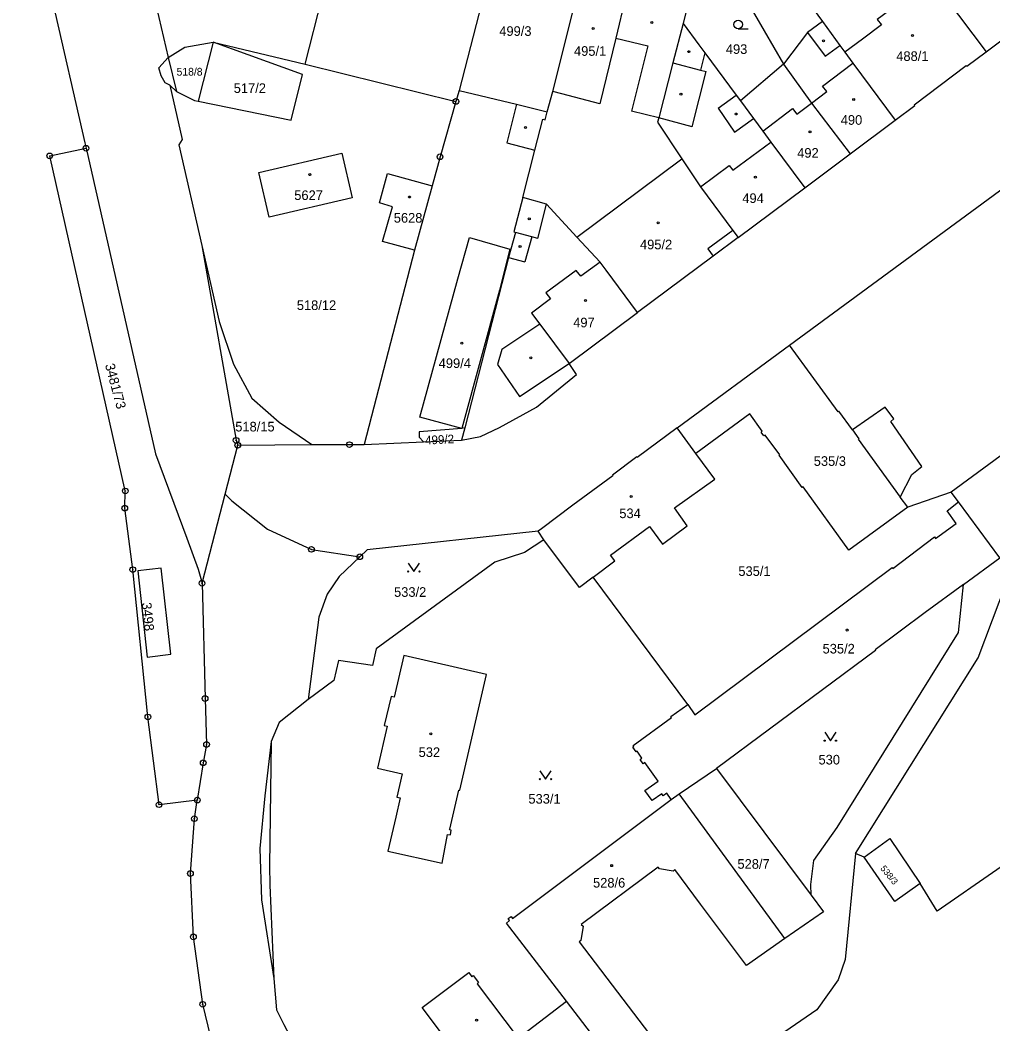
# Model space of a CAD drawing. Extents: x -733394 to -722299, y -1082822 to -1075049.
# Drawn here: x -728736.2 to -728564.5, y -1079876.8 to -1079699.5 of the extents above; entities that cross this region are included whole.
import ezdxf

# ---------------------------------------------------------------- set-up
doc = ezdxf.new("R2010")
doc.units = 0
for name, color, linetype in [('Hranice parcel', 7, 'Continuous'), ('Parcelní čísla', 7, 'Continuous'), ('Vnitřní kresba', 7, 'Continuous'), ('Značky bodu BP', 7, 'Continuous'), ('Značky budov', 7, 'Continuous'), ('Značky kultur', 7, 'Continuous')]:
    doc.layers.add(name, color=color, linetype=linetype)

msp = doc.modelspace()

# ---------------------------------------------------------------- linework, layer by layer
at = {"layer": 'Hranice parcel'}
for p, q in [((-728600.37, -1079756.93), (-728481.03, -1079668.98)), ((-728685.9, -1079707.28), (-728676.7, -1079670.77)), ((-728615.13, -1079683.71), (-728601.43, -1079707.28)), ((-728600.39, -1079691.8), (-728594.58, -1079699.77)), ((-728565.68, -1079705.08), (-728549.64, -1079693.06)), ((-728712.73, -1079694.7), (-728710.07, -1079706.09)), ((-728574.05, -1079693.93), (-728565.68, -1079705.08)), ((-728618.23, -1079696.26), (-728619.19, -1079700.08)), ((-728702.17, -1079703.39), (-728704.81, -1079713.82)), ((-728702.17, -1079703.39), (-728685.9, -1079707.28)), ((-728710.07, -1079706.09), (-728708.63, -1079712.09)), ((-728685.9, -1079707.28), (-728659.29, -1079713.87)), ((-728601.43, -1079707.28), (-728609.07, -1079713.76)), ((-728589.67, -1079723.1), (-728581.71, -1079717.14)), ((-728597.69, -1079729.14), (-728589.67, -1079723.1)), ((-728637.95, -1079737.82), (-728619.38, -1079724.02)), ((-728663.46, -1079728.74), (-728666.6, -1079740.15)), ((-728609.45, -1079737.9), (-728597.69, -1079729.14)), ((-728666.6, -1079740.15), (-728675.49, -1079774.47)), ((-728620.2, -1079771.52), (-728600.37, -1079756.93)), ((-728657.74, -1079771.52), (-728658.3, -1079773.67)), ((-728616.93, -1079776.02), (-728620.2, -1079771.52)), ((-728700.04, -1079783.2), (-728697.81, -1079774.58)), ((-728697.81, -1079774.58), (-728684.74, -1079774.48)), ((-728675.49, -1079774.47), (-728665.01, -1079773.97)), ((-728665.01, -1079773.97), (-728658.3, -1079773.67)), ((-728704.12, -1079798.96), (-728700.04, -1079783.2)), ((-728571.82, -1079782.9), (-728579.52, -1079785.52)), ((-728570.57, -1079784.59), (-728571.82, -1079782.9)), ((-728563.27, -1079794.45), (-728570.57, -1079784.59)), ((-728643.75, -1079791.27), (-728644.78, -1079789.76)), ((-728569.69, -1079799.17), (-728563.27, -1079794.45)), ((-728618.36, -1079820.39), (-728635.06, -1079797.91)), ((-728619.87, -1079836.15), (-728613.3, -1079831.66)), ((-728613.3, -1079831.66), (-728596.59, -1079854.04)), ((-728621.29, -1079837.13), (-728619.87, -1079836.15)), ((-728601.22, -1079861.71), (-728619.87, -1079836.15)), ((-728587.19, -1079847.34), (-728588.73, -1079846.69)), ((-728648.31, -1079879.32), (-728639.77, -1079872.79))]:
    msp.add_line(p, q, dxfattribs=at)
for points in [[(-728736.24, -1079671.17), (-728724.82, -1079721.18), (-728724.6, -1079722.13)], [(-728647.5, -1079730.8), (-728645.37, -1079722.49), (-728643.96, -1079716.99), (-728643.51, -1079717.1), (-728643.19, -1079715.67), (-728642.19, -1079712.1), (-728638.7, -1079698.26), (-728637.07, -1079691.73), (-728636.65, -1079691.83)], [(-728574.62, -1079693.18), (-728581.09, -1079698.03), (-728581.81, -1079697.07), (-728584.9, -1079699.36), (-728584.17, -1079700.33), (-728587.53, -1079702.85), (-728590.64, -1079705.18)], [(-728654.26, -1079694.49), (-728658.73, -1079711.9), (-728659.29, -1079713.87)], [(-728619.19, -1079700.08), (-728620.96, -1079707.02), (-728623.45, -1079716.76), (-728623.71, -1079717.51), (-728619.38, -1079724.02)], [(-728619.19, -1079700.08), (-728616.37, -1079703.87), (-728615.34, -1079705.27), (-728609.8, -1079712.78), (-728609.07, -1079713.76)], [(-728594.58, -1079699.77), (-728597.21, -1079701.68), (-728601.43, -1079707.28)], [(-728594.58, -1079699.77), (-728591.52, -1079703.97), (-728590.64, -1079705.18)], [(-728461.74, -1079701.6), (-728474.16, -1079710.73), (-728473.29, -1079711.95), (-728473.96, -1079712.56), (-728473.83, -1079712.73), (-728488.37, -1079723.47), (-728489.45, -1079722.05), (-728493.6, -1079725.15), (-728492.57, -1079726.56), (-728507.86, -1079737.87), (-728508.12, -1079737.52), (-728514.31, -1079742.12), (-728515.03, -1079741.15), (-728518.25, -1079743.53), (-728517.53, -1079744.5), (-728523.81, -1079749.15), (-728523.56, -1079749.48), (-728558.3, -1079775.23), (-728559.4, -1079773.75), (-728571.82, -1079782.9)], [(-728710.07, -1079706.09), (-728707.17, -1079704.26), (-728702.17, -1079703.39)], [(-728704.81, -1079713.82), (-728688.39, -1079717.19), (-728686.35, -1079709.09), (-728702.17, -1079703.39)], [(-728590.64, -1079705.18), (-728589.19, -1079707.1), (-728581.71, -1079717.14)], [(-728581.71, -1079717.14), (-728578.28, -1079714.56), (-728578.36, -1079714.44), (-728569.18, -1079707.53), (-728569.09, -1079707.65), (-728565.68, -1079705.08)], [(-728601.43, -1079707.28), (-728596.5, -1079714.16), (-728589.67, -1079723.1)], [(-728708.63, -1079712.09), (-728709.79, -1079711.01), (-728707.61, -1079720.57), (-728708.21, -1079721.53), (-728704.16, -1079739.32)], [(-728708.63, -1079712.09), (-728705.47, -1079713.67), (-728704.81, -1079713.82)], [(-728659.29, -1079713.87), (-728662.09, -1079723.64), (-728663.46, -1079728.74)], [(-728609.07, -1079713.76), (-728606.77, -1079716.88), (-728605.12, -1079719.11), (-728603.68, -1079721.05), (-728597.69, -1079729.14)], [(-728704.95, -1079837.26), (-728711.71, -1079838.07), (-728713.67, -1079822.58), (-728716.34, -1079796.56), (-728717.75, -1079785.69), (-728717.66, -1079782.66), (-728731.01, -1079723.47), (-728724.6, -1079722.13)], [(-728724.6, -1079722.13), (-728712.34, -1079776.13), (-728706.81, -1079790.97), (-728704.81, -1079796.45), (-728704.12, -1079798.96)], [(-728692.28, -1079734.29), (-728694.09, -1079726.39), (-728679.41, -1079723.02), (-728677.59, -1079730.91), (-728692.28, -1079734.29)], [(-728619.38, -1079724.02), (-728616.09, -1079728.97), (-728614.93, -1079730.55), (-728610.39, -1079736.64), (-728609.45, -1079737.9)], [(-728666.6, -1079740.15), (-728672.24, -1079738.61), (-728670.5, -1079732.46), (-728672.81, -1079731.78), (-728671.39, -1079726.56), (-728663.46, -1079728.74)], [(-728647.5, -1079730.8), (-728649.07, -1079736.92), (-728648.79, -1079736.99), (-728649.98, -1079741.42), (-728657.74, -1079771.52)], [(-728637.95, -1079737.82), (-728643.28, -1079732.02), (-728647.5, -1079730.8)], [(-728651.59, -1079747.22), (-728658.27, -1079771.62), (-728665.65, -1079769.6), (-728658.97, -1079745.2), (-728656.9, -1079737.89), (-728649.76, -1079739.93), (-728651.59, -1079747.22)], [(-728627.22, -1079751.12), (-728632.77, -1079743.66), (-728633.8, -1079742.27), (-728637.95, -1079737.82)], [(-728609.45, -1079737.9), (-728613.85, -1079741.18), (-728627.22, -1079751.12)], [(-728704.16, -1079739.32), (-728701.09, -1079752.75), (-728698.56, -1079760.27), (-728695.31, -1079766.27), (-728690.52, -1079770.5), (-728684.74, -1079774.48)], [(-728704.16, -1079739.32), (-728698.1, -1079773.71), (-728697.81, -1079774.58)], [(-728658.3, -1079773.67), (-728654.94, -1079773.04), (-728651.58, -1079771.48), (-728645.08, -1079767.85), (-728637.99, -1079762.09), (-728639.3, -1079760.14), (-728627.22, -1079751.12)], [(-728579.52, -1079785.52), (-728580.83, -1079783.73), (-728578.78, -1079779.77), (-728577.02, -1079778.36), (-728582.48, -1079770.38), (-728581.95, -1079769.92), (-728583.49, -1079767.87), (-728589.28, -1079771.89), (-728591.7, -1079768.57), (-728591.82, -1079768.66), (-728600.37, -1079756.93)], [(-728579.52, -1079785.52), (-728589.92, -1079793.09), (-728597.99, -1079781.94), (-728598.13, -1079782.04), (-728602.24, -1079776.36), (-728602.1, -1079776.27), (-728604.69, -1079772.8), (-728604.91, -1079772.95), (-728605.41, -1079772.26), (-728605.2, -1079772.1), (-728607.42, -1079769.04), (-728616.93, -1079776.02)], [(-728657.74, -1079771.52), (-728658.27, -1079771.62), (-728665.8, -1079772.22), (-728665.75, -1079773.15), (-728665.01, -1079773.97)], [(-728620.2, -1079771.52), (-728627.31, -1079776.75), (-728627.36, -1079776.66), (-728631.66, -1079779.89), (-728631.6, -1079779.98), (-728638.64, -1079785.16), (-728644.18, -1079789.32), (-728644.78, -1079789.76)], [(-728684.74, -1079774.48), (-728678.09, -1079774.48), (-728675.49, -1079774.47)], [(-728635.06, -1079797.91), (-728631.22, -1079794.99), (-728631.98, -1079794.01), (-728625.09, -1079788.96), (-728622.82, -1079792.05), (-728618.44, -1079788.84), (-728620.71, -1079785.65), (-728613.58, -1079780.58), (-728616.93, -1079776.02)], [(-728700.04, -1079783.2), (-728698.86, -1079784.41), (-728692.53, -1079789.41), (-728684.8, -1079792.98), (-728676.26, -1079794.29)], [(-728618.36, -1079820.39), (-728617.08, -1079822.2), (-728582.27, -1079796.16), (-728582.12, -1079796.36), (-728574.81, -1079790.77), (-728574.6, -1079791.05), (-728570.98, -1079788.4), (-728572.57, -1079786.16), (-728570.57, -1079784.59)], [(-728644.78, -1079789.76), (-728674.95, -1079793.03), (-728676.26, -1079794.29)], [(-728643.75, -1079791.27), (-728647.19, -1079793.53), (-728652.44, -1079795.23), (-728673.39, -1079810.55), (-728674.01, -1079813.51), (-728680, -1079812.61), (-728680.83, -1079816.15), (-728685.38, -1079819.49)], [(-728635.06, -1079797.91), (-728637.47, -1079799.74), (-728643.75, -1079791.27)], [(-728676.26, -1079794.29), (-728679.91, -1079797.78), (-728682.01, -1079800.9), (-728683.5, -1079804.93), (-728685.38, -1079819.49)], [(-728711.35, -1079796.28), (-728715.46, -1079796.75), (-728713.82, -1079812.01), (-728709.6, -1079811.46), (-728711.35, -1079796.28)], [(-728704.12, -1079798.96), (-728703.58, -1079819.32), (-728703.32, -1079827.43), (-728703.91, -1079830.67), (-728704.95, -1079837.26)], [(-728569.69, -1079799.17), (-728576.43, -1079804.11), (-728585.24, -1079810.75), (-728585.18, -1079810.83), (-728613.3, -1079831.66)], [(-728596.59, -1079854.04), (-728596.65, -1079852.18), (-728596.07, -1079847.92), (-728591.97, -1079842.08), (-728570.58, -1079807.66), (-728569.69, -1079799.17)], [(-728588.73, -1079846.69), (-728567.06, -1079812.14), (-728562.01, -1079798.71)], [(-728661.74, -1079848.42), (-728660.75, -1079843.31), (-728660.27, -1079843.41), (-728660.11, -1079842.58), (-728660.4, -1079842.52), (-728660.38, -1079842.42), (-728658.76, -1079835.48), (-728658.62, -1079835.52), (-728653.86, -1079815.1), (-728668.48, -1079811.7), (-728670.19, -1079819.07), (-728670.73, -1079818.95), (-728671.93, -1079824.1), (-728671.41, -1079824.23), (-728673.12, -1079831.61), (-728668.78, -1079832.62), (-728669.73, -1079836.74), (-728669.12, -1079836.88), (-728669.92, -1079840.3), (-728671.3, -1079846.27), (-728661.74, -1079848.42)], [(-728685.38, -1079819.49), (-728690.49, -1079823.57), (-728691.93, -1079826.93), (-728692.21, -1079848.9), (-728692.12, -1079852.26), (-728691.43, -1079868.79), (-728690.98, -1079874.32), (-728689.69, -1079876.88), (-728686.54, -1079882.81), (-728681.95, -1079889.46), (-728677.3, -1079895.69), (-728672.31, -1079904.55), (-728667.7, -1079914.61), (-728664.97, -1079923.35), (-728665.49, -1079935.45), (-728666.25, -1079938.93), (-728675.19, -1079953.37), (-728681.79, -1079965.59), (-728682.06, -1079967.06)], [(-728621.29, -1079837.13), (-728622.07, -1079836.02), (-728622.71, -1079836.48), (-728622.94, -1079836.16), (-728624.66, -1079837.36), (-728625.92, -1079835.56), (-728623.6, -1079833.94), (-728625.92, -1079830.61), (-728626.24, -1079830.84), (-728626.78, -1079830.08), (-728626.45, -1079829.85), (-728627.29, -1079828.64), (-728627.46, -1079828.76), (-728628.06, -1079827.91), (-728627.9, -1079827.79), (-728628.01, -1079827.63), (-728621.21, -1079822.7), (-728621.36, -1079822.5), (-728618.36, -1079820.39)], [(-728542.72, -1079834.95), (-728574.3, -1079856.88), (-728577.3, -1079851.98)], [(-728692.61, -1079900.87), (-728697.81, -1079892.26), (-728701.6, -1079883.03), (-728704, -1079873.33), (-728705.64, -1079861.43), (-728706.17, -1079850.23), (-728705.47, -1079840.55), (-728704.95, -1079837.26)], [(-728639.77, -1079872.79), (-728650.37, -1079858.97), (-728649.8, -1079858.54), (-728650.06, -1079858.2), (-728649.54, -1079857.81), (-728649.27, -1079858.16), (-728621.29, -1079837.13)], [(-728587.19, -1079847.34), (-728582.69, -1079844.05), (-728577.3, -1079851.98)], [(-728588.73, -1079846.69), (-728590.57, -1079865.42), (-728591.78, -1079868.98), (-728595.58, -1079874.31), (-728604.06, -1079880.15), (-728602.36, -1079880.57), (-728608.62, -1079902.34), (-728611.09, -1079901.64)], [(-728577.3, -1079851.98), (-728581.81, -1079855.16), (-728587.19, -1079847.34)], [(-728601.22, -1079861.71), (-728607.99, -1079866.45), (-728616.08, -1079855.63), (-728620.63, -1079849.54), (-728620.94, -1079849.84), (-728623.34, -1079849.43), (-728623.55, -1079849.1), (-728637.15, -1079859.21), (-728636.84, -1079859.55), (-728637.25, -1079862.05), (-728637.54, -1079862.27), (-728620.25, -1079885.03), (-728622.03, -1079886.35), (-728621.8, -1079886.66), (-728622.34, -1079887.06), (-728622.57, -1079886.76), (-728626.69, -1079889.83), (-728639.77, -1079872.79)], [(-728596.59, -1079854.04), (-728594.37, -1079857.01), (-728601.22, -1079861.71)], [(-728656.47, -1079885.56), (-728665.24, -1079873.88), (-728657.03, -1079867.74), (-728656.49, -1079868.45), (-728656.22, -1079868.25), (-728655.28, -1079869.5), (-728655.55, -1079869.7), (-728648.31, -1079879.32)]]:
    msp.add_lwpolyline(points, dxfattribs=at)
at = {"layer": 'Vnitřní kresba'}
for p, q in [((-728628.91, -1079693.69), (-728631.07, -1079702.68)), ((-728597.21, -1079701.68), (-728594.11, -1079705.86)), ((-728631.07, -1079702.68), (-728633.85, -1079714.28)), ((-728631.07, -1079702.68), (-728625.43, -1079704.03)), ((-728625.43, -1079704.03), (-728628.31, -1079715.6)), ((-728594.11, -1079705.86), (-728591.52, -1079703.97)), ((-728615.34, -1079705.27), (-728616.1, -1079708.32)), ((-728620.96, -1079707.02), (-728616.1, -1079708.32)), ((-728594.55, -1079711.14), (-728589.19, -1079707.1)), ((-728617.56, -1079718.33), (-728615.11, -1079708.57)), ((-728616.1, -1079708.32), (-728615.11, -1079708.57)), ((-728593.82, -1079712.09), (-728594.55, -1079711.14)), ((-728658.73, -1079711.9), (-728648.62, -1079714.35)), ((-728640.56, -1079712.53), (-728642.19, -1079712.1)), ((-728633.85, -1079714.28), (-728640.56, -1079712.53)), ((-728613, -1079715.05), (-728609.8, -1079712.78)), ((-728596.5, -1079714.16), (-728593.82, -1079712.09)), ((-728648.62, -1079714.35), (-728650.32, -1079721.16)), ((-728648.62, -1079714.35), (-728643.19, -1079715.67)), ((-728599.08, -1079716.11), (-728596.5, -1079714.16)), ((-728623.45, -1079716.76), (-728628.31, -1079715.6)), ((-728613, -1079715.05), (-728610.09, -1079719.27)), ((-728605.12, -1079719.11), (-728599.84, -1079715.13)), ((-728599.84, -1079715.13), (-728599.08, -1079716.11)), ((-728617.56, -1079718.33), (-728623.45, -1079716.76)), ((-728610.09, -1079719.27), (-728606.77, -1079716.88)), ((-728650.32, -1079721.16), (-728645.37, -1079722.49)), ((-728610.37, -1079725.98), (-728603.68, -1079721.05)), ((-728616.09, -1079728.97), (-728611.05, -1079725.17)), ((-728611.05, -1079725.17), (-728610.37, -1079725.98)), ((-728644.85, -1079738.06), (-728643.28, -1079732.02)), ((-728645.89, -1079737.78), (-728648.79, -1079736.99)), ((-728645.89, -1079737.78), (-728647.1, -1079742.2)), ((-728644.85, -1079738.06), (-728645.89, -1079737.78)), ((-728610.39, -1079736.64), (-728614.79, -1079739.92)), ((-728649.98, -1079741.42), (-728647.1, -1079742.2)), ((-728614.79, -1079739.92), (-728613.85, -1079741.18)), ((-728633.8, -1079742.27), (-728637.21, -1079744.75)), ((-728638.05, -1079743.73), (-728643.4, -1079747.67)), ((-728637.21, -1079744.75), (-728638.05, -1079743.73)), ((-728643.4, -1079747.67), (-728642.61, -1079748.73)), ((-728642.61, -1079748.73), (-728645.96, -1079751.23)), ((-728645.96, -1079751.23), (-728644.45, -1079753.18)), ((-728644.45, -1079753.18), (-728651.2, -1079757.68)), ((-728644.45, -1079753.18), (-728639.3, -1079760.14)), ((-728651.2, -1079757.68), (-728651.94, -1079760.33)), ((-728651.94, -1079760.33), (-728648.09, -1079765.97)), ((-728648.09, -1079765.97), (-728639.3, -1079760.14)), ((-728589.28, -1079771.89), (-728588.14, -1079773.44)), ((-728588.14, -1079773.44), (-728588.27, -1079773.52)), ((-728588.27, -1079773.52), (-728580.83, -1079783.73)), ((-728691.93, -1079826.93), (-728693.02, -1079836.53)), ((-728693.02, -1079836.53), (-728693.91, -1079845.81)), ((-728693.91, -1079845.81), (-728693.59, -1079854.89)), ((-728693.59, -1079854.89), (-728691.43, -1079868.79))]:
    msp.add_line(p, q, dxfattribs=at)
msp.add_lwpolyline([(-728709.79, -1079711.01), (-728710.63, -1079710.58), (-728711.33, -1079709.36), (-728711.74, -1079707.91), (-728710.07, -1079706.09)], dxfattribs=at)
at = {"layer": 'Značky bodu BP'}
for centre, radius in [((-728659.29, -1079713.87), 0.5), ((-728659.29, -1079713.87), 0.0303), ((-728724.6, -1079722.13), 0.5), ((-728731.01, -1079723.47), 0.5), ((-728731.01, -1079723.47), 0.0303), ((-728724.6, -1079722.13), 0.0303), ((-728662.09, -1079723.64), 0.5), ((-728662.09, -1079723.64), 0.0303), ((-728698.1, -1079773.71), 0.5), ((-728697.81, -1079774.58), 0.5), ((-728698.1, -1079773.71), 0.0303), ((-728697.81, -1079774.58), 0.0303), ((-728678.09, -1079774.48), 0.5), ((-728678.09, -1079774.48), 0.0303), ((-728717.66, -1079782.66), 0.5), ((-728717.66, -1079782.66), 0.0303), ((-728717.75, -1079785.69), 0.5), ((-728717.75, -1079785.69), 0.0303), ((-728684.8, -1079792.98), 0.5), ((-728684.8, -1079792.98), 0.0303), ((-728676.26, -1079794.29), 0.5), ((-728676.26, -1079794.29), 0.0303), ((-728716.34, -1079796.56), 0.5), ((-728716.34, -1079796.56), 0.0303), ((-728704.12, -1079798.96), 0.5), ((-728704.12, -1079798.96), 0.0303), ((-728703.58, -1079819.32), 0.5), ((-728703.58, -1079819.32), 0.0303), ((-728713.67, -1079822.58), 0.5), ((-728713.67, -1079822.58), 0.0303), ((-728703.32, -1079827.43), 0.5), ((-728703.32, -1079827.43), 0.0303), ((-728703.91, -1079830.67), 0.5), ((-728703.91, -1079830.67), 0.0303), ((-728704.95, -1079837.26), 0.5), ((-728704.95, -1079837.26), 0.0303), ((-728711.71, -1079838.07), 0.5), ((-728711.71, -1079838.07), 0.0303), ((-728705.47, -1079840.55), 0.5), ((-728705.47, -1079840.55), 0.0303), ((-728706.17, -1079850.23), 0.5), ((-728706.17, -1079850.23), 0.0303), ((-728705.64, -1079861.43), 0.5), ((-728705.64, -1079861.43), 0.0303), ((-728704, -1079873.33), 0.5), ((-728704, -1079873.33), 0.0303)]:
    msp.add_circle(centre, radius, dxfattribs=at)
at = {"layer": 'Značky budov'}
for centre in [(-728624.7, -1079699.92), (-728635.05, -1079701), (-728578.66, -1079702.21), (-728594.38, -1079703.14), (-728618.17, -1079705.07), (-728619.55, -1079712.58), (-728589.06, -1079713.54), (-728609.8, -1079716.08), (-728647.01, -1079718.46), (-728596.77, -1079719.25), (-728685.06, -1079726.79), (-728606.42, -1079727.25), (-728667.5, -1079730.74), (-728646.33, -1079734.59), (-728623.58, -1079735.3), (-728647.97, -1079739.5), (-728636.43, -1079749.04), (-728658.26, -1079756.55), (-728646.05, -1079759.16), (-728628.35, -1079783.66), (-728590.21, -1079807.22), (-728663.7, -1079825.56), (-728631.79, -1079848.84), (-728655.63, -1079876.11)]:
    msp.add_circle(centre, 0.175, dxfattribs=at)
at = {"layer": 'Značky kultur'}
msp.add_line((-728609.45, -1079701.03), (-728607.7, -1079701.03), dxfattribs=at)
for points in [[(-728667.73, -1079795.39), (-728666.73, -1079796.89), (-728665.73, -1079795.39)], [(-728594.17, -1079825.27), (-728593.17, -1079826.77), (-728592.17, -1079825.27)], [(-728644.48, -1079832.07), (-728643.48, -1079833.57), (-728642.48, -1079832.07)]]:
    msp.add_lwpolyline(points, dxfattribs=at)
for centre, radius in [((-728609.45, -1079700.28), 0.75), ((-728667.73, -1079796.89), 0.1), ((-728665.73, -1079796.89), 0.1), ((-728594.17, -1079826.77), 0.1), ((-728592.17, -1079826.77), 0.1), ((-728644.48, -1079833.57), 0.1), ((-728642.48, -1079833.57), 0.1)]:
    msp.add_circle(centre, radius, dxfattribs=at)

# ---------------------------------------------------------------- texts
at = {"layer": 'Parcelní čísla'}
for s, height, p in [('499/3', 1.7, (-728651.63, -1079702.28)), ('495/1', 1.7, (-728638.44, -1079705.8)), ('493', 1.7, (-728611.63, -1079705.47)), ('488/1', 1.7, (-728581.54, -1079706.71)), ('518/8', 1.37, (-728708.61, -1079709.3)), ('517/2', 1.7, (-728698.52, -1079712.36)), ('490', 1.7, (-728591.34, -1079717.98)), ('492', 1.7, (-728599.03, -1079723.8)), ('5627', 1.7, (-728687.83, -1079731.27)), ('494', 1.7, (-728608.72, -1079731.8)), ('5628', 1.7, (-728670.26, -1079735.27)), ('495/2', 1.7, (-728626.79, -1079739.98)), ('518/12', 1.7, (-728687.38, -1079750.7)), ('497', 1.7, (-728638.58, -1079753.76)), ('499/4', 1.7, (-728662.33, -1079760.95)), ('518/15', 1.7, (-728698.25, -1079772.15)), ('535/3', 1.7, (-728596.11, -1079778.23)), ('534', 1.7, (-728630.44, -1079787.46)), ('535/1', 1.7, (-728609.42, -1079797.67)), ('533/2', 1.7, (-728670.21, -1079801.36)), ('535/2', 1.7, (-728594.55, -1079811.37)), ('532', 1.7, (-728665.87, -1079829.65)), ('530', 1.7, (-728595.27, -1079830.97)), ('533/1', 1.7, (-728646.49, -1079837.89)), ('528/7', 1.7, (-728609.58, -1079849.39)), ('528/6', 1.7, (-728635.08, -1079852.71))]:
    msp.add_text(s, height=height, dxfattribs=at).set_placement(p)
for s, height, rotation, p in [('3481/73', 1.7, 285, (-728721.26, -1079760.39)), ('499/2', 1.53, 3, (-728664.69, -1079774.48)), ('3498', 1.7, 276, (-728714.76, -1079802.44)), ('538/3', 1.139, 309, (-728584.42, -1079849.36))]:
    msp.add_text(s, height=height, rotation=rotation, dxfattribs=at).set_placement(p)

doc.saveas('drawing.dxf')
